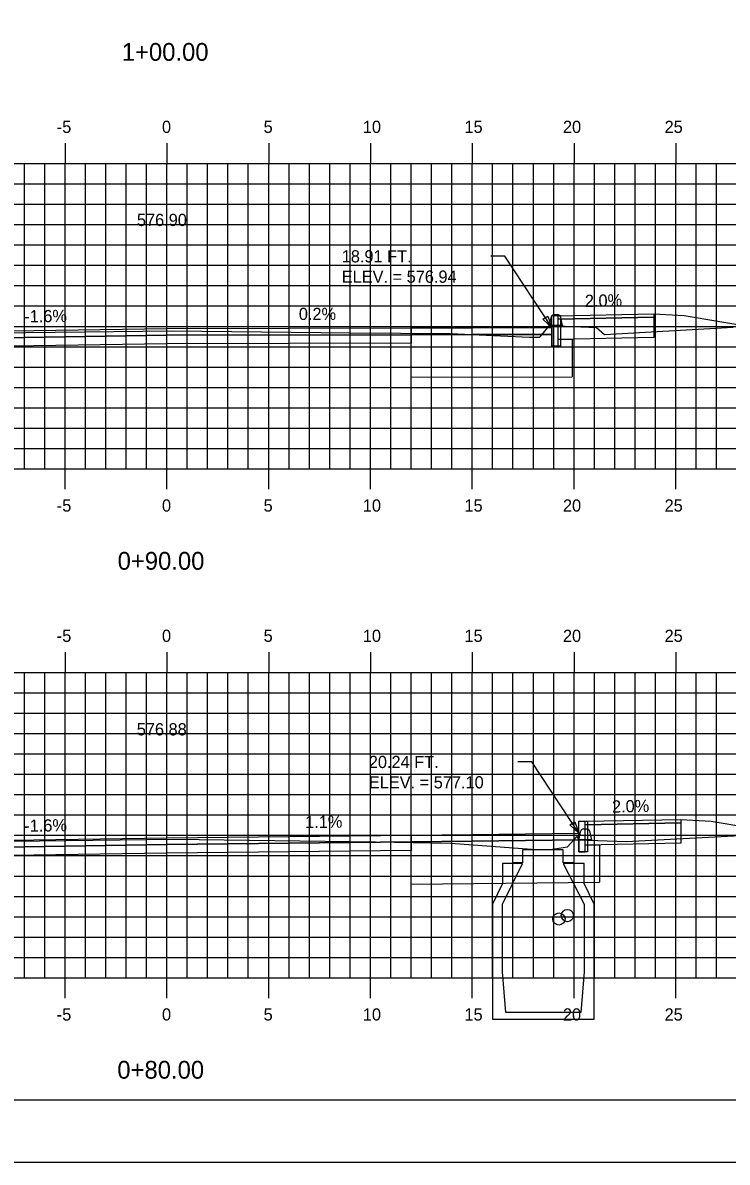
# Model space of a CAD drawing. Extents: x 1048565 to 1048735, y 781387 to 781497.
# Drawn here: x 1048640.8 to 1048675.4, y 781387.3 to 781443.3 of the extents above; entities that cross this region are included whole.
import ezdxf

# ---------------------------------------------------------------- set-up
doc = ezdxf.new("R2010")
doc.units = 0
for name, color, linetype in [('ANNOTATION', 7, 'Continuous'), ('BORDER', 7, 'Continuous'), ('D_Curb_Type1_Lt', 7, 'Continuous'), ('D_Roadway_Berm', 7, 'Continuous'), ('D_Roadway_Centerline', 7, 'Continuous'), ('D_Roadway_Centerline_Text', 7, 'Continuous'), ('D_Roadway_Edge_Shoulder', 7, 'Continuous'), ('D_Roadway_Edge_TW', 7, 'Continuous'), ('D_Roadway_Pavement', 7, 'Continuous'), ('D_Roadway_Sidewalks_Paved', 7, 'Continuous'), ('D_Roadway_SlopeLines', 7, 'Continuous'), ('D_Roadway_SubGrade', 7, 'Continuous'), ('D_Text_Standard', 7, 'Continuous'), ('H_V ANNOTATION', 7, 'Continuous'), ('MAJOR', 7, 'Continuous'), ('MINOR', 7, 'Continuous'), ('PLOT BOUNDARY', 7, 'Continuous'), ('S_Curb_Type_3', 7, 'Continuous'), ('S_Drainage_CB', 7, 'Continuous'), ('S_Drainage_Invert', 7, 'Continuous'), ('S_Roadway_Centerline', 7, 'Continuous')]:
    doc.layers.add(name, color=color, linetype=linetype)

msp = doc.modelspace()

# ---------------------------------------------------------------- linework, layer by layer
at = {"layer": 'BORDER'}
msp.add_lwpolyline([(1048572.876, 781390.375), (1048732.876, 781390.375), (1048732.876, 781495.375), (1048572.876, 781495.375)], close=True, dxfattribs=at)
at = {"layer": 'D_Curb_Type1_Lt'}
for points in [[(1048667.204, 781428.902), (1048667.204, 781427.402), (1048666.787, 781427.402), (1048666.787, 781428.902)], [(1048668.534, 781404.063), (1048668.534, 781402.563), (1048668.117, 781402.563), (1048668.117, 781404.063)]]:
    msp.add_lwpolyline(points, close=True, dxfattribs=at)
at = {"layer": 'D_Roadway_Berm'}
for points in [[(1048671.788, 781428.993), (1048673.288, 781428.903)], [(1048673.118, 781404.155), (1048674.618, 781404.065)]]:
    msp.add_lwpolyline(points, dxfattribs=at)
at = {"layer": 'D_Roadway_Edge_Shoulder'}
for points in [[(1048659.876, 781428.3), (1048662.876, 781428.307), (1048666.787, 781428.316), (1048666.787, 781427.983), (1048662.876, 781427.973), (1048659.876, 781427.966)], [(1048659.876, 781403.385), (1048662.876, 781403.419), (1048668.117, 781403.478), (1048668.117, 781403.144), (1048662.876, 781403.086), (1048659.876, 781403.052)]]:
    msp.add_lwpolyline(points, close=True, dxfattribs=at)
at = {"layer": 'D_Roadway_Edge_TW'}
for points in [[(1048635.876, 781427.752), (1048635.876, 781428.085), (1048647.876, 781428.271), (1048659.876, 781428.3), (1048659.876, 781427.966), (1048647.876, 781427.938)], [(1048635.876, 781402.73), (1048635.876, 781403.063), (1048647.876, 781403.251), (1048659.876, 781403.385), (1048659.876, 781403.052), (1048647.876, 781402.918)]]:
    msp.add_lwpolyline(points, close=True, dxfattribs=at)
at = {"layer": 'D_Roadway_Pavement'}
for points in [[(1048635.876, 781427.335), (1048635.876, 781427.752), (1048647.876, 781427.938), (1048659.876, 781427.966), (1048659.876, 781427.55), (1048647.876, 781427.521)], [(1048635.876, 781402.314), (1048635.876, 781402.73), (1048647.876, 781402.918), (1048659.876, 781403.052), (1048659.876, 781402.636), (1048647.876, 781402.501)]]:
    msp.add_lwpolyline(points, close=True, dxfattribs=at)
at = {"layer": 'D_Roadway_Sidewalks_Paved'}
for points in [[(1048667.088, 781428.899), (1048671.788, 781428.993), (1048671.788, 781428.826), (1048667.088, 781428.732)], [(1048668.418, 781404.061), (1048673.118, 781404.155), (1048673.118, 781403.988), (1048668.418, 781403.894)]]:
    msp.add_lwpolyline(points, close=True, dxfattribs=at)
at = {"layer": 'D_Roadway_SlopeLines'}
for points in [[(1048673.288, 781428.903), (1048676.593, 781428.352)], [(1048674.618, 781404.065), (1048678.119, 781403.481)]]:
    msp.add_lwpolyline(points, dxfattribs=at)
at = {"layer": 'D_Roadway_SubGrade'}
for p, q in [((1048659.876, 781425.883), (1048667.787, 781425.902)), ((1048659.876, 781400.969), (1048669.117, 781401.072))]:
    msp.add_line(p, q, dxfattribs=at)
for points in [[(1048667.088, 781428.732), (1048671.788, 781428.826), (1048671.788, 781427.826), (1048667.088, 781427.732)], [(1048668.418, 781403.894), (1048673.118, 781403.988), (1048673.118, 781402.988), (1048668.418, 781402.894)]]:
    msp.add_lwpolyline(points, close=True, dxfattribs=at)
for points in [[(1048659.876, 781425.883), (1048659.876, 781427.966), (1048659.876, 781427.966), (1048662.876, 781427.973), (1048666.787, 781427.983), (1048666.787, 781427.399), (1048667.097, 781427.399), (1048667.088, 781427.732), (1048667.787, 781427.746), (1048667.787, 781425.902)], [(1048659.876, 781400.969), (1048659.876, 781403.052), (1048659.876, 781403.052), (1048662.876, 781403.086), (1048668.117, 781403.144), (1048668.117, 781402.561), (1048668.427, 781402.561), (1048668.418, 781402.894), (1048669.117, 781402.908), (1048669.117, 781401.072)]]:
    msp.add_lwpolyline(points, dxfattribs=at)
at = {"layer": 'D_Text_Standard'}
for points in [[(1048666.787, 781428.316), (1048664.47, 781431.816), (1048663.79, 781431.816)], [(1048668.117, 781403.478), (1048665.8, 781406.978), (1048665.12, 781406.978)]]:
    msp.add_lwpolyline(points, dxfattribs=at)
for points in [[(1048666.787, 781428.316), (1048666.344, 781428.721), (1048666.587, 781428.882)], [(1048668.117, 781403.478), (1048667.675, 781403.883), (1048667.917, 781404.043)]]:
    msp.add_lwpolyline(points, close=True, dxfattribs=at)
at = {"layer": 'MAJOR'}
for p, q in [((1048642.876, 781437.377), (1048642.876, 781436.375)), ((1048647.876, 781437.377), (1048647.876, 781436.375)), ((1048652.876, 781437.377), (1048652.876, 781436.375)), ((1048657.876, 781437.377), (1048657.876, 781436.375)), ((1048662.876, 781437.377), (1048662.876, 781436.375)), ((1048667.876, 781437.377), (1048667.876, 781436.375)), ((1048672.876, 781437.377), (1048672.876, 781436.375)), ((1048577.876, 781436.375), (1048717.876, 781436.375)), ((1048577.876, 781436.375), (1048717.876, 781436.375)), ((1048642.876, 781421.375), (1048642.876, 781436.375)), ((1048647.876, 781421.375), (1048647.876, 781436.375)), ((1048652.876, 781421.375), (1048652.876, 781436.375)), ((1048657.876, 781421.375), (1048657.876, 781436.375)), ((1048662.876, 781421.375), (1048662.876, 781436.375)), ((1048667.876, 781421.375), (1048667.876, 781436.375)), ((1048672.876, 781421.375), (1048672.876, 781436.375)), ((1048577.876, 781431.375), (1048717.876, 781431.375)), ((1048577.876, 781426.375), (1048717.876, 781426.375)), ((1048577.876, 781421.375), (1048717.876, 781421.375)), ((1048577.876, 781421.375), (1048717.876, 781421.375)), ((1048642.876, 781420.373), (1048642.876, 781421.375)), ((1048647.876, 781420.373), (1048647.876, 781421.375)), ((1048652.876, 781420.373), (1048652.876, 781421.375)), ((1048657.876, 781420.373), (1048657.876, 781421.375)), ((1048662.876, 781420.373), (1048662.876, 781421.375)), ((1048667.876, 781420.373), (1048667.876, 781421.375)), ((1048672.876, 781420.373), (1048672.876, 781421.375)), ((1048642.876, 781412.377), (1048642.876, 781411.375)), ((1048647.876, 781412.377), (1048647.876, 781411.375)), ((1048652.876, 781412.377), (1048652.876, 781411.375)), ((1048657.876, 781412.377), (1048657.876, 781411.375)), ((1048662.876, 781412.377), (1048662.876, 781411.375)), ((1048667.876, 781412.377), (1048667.876, 781411.375)), ((1048672.876, 781412.377), (1048672.876, 781411.375)), ((1048577.876, 781411.375), (1048717.876, 781411.375)), ((1048577.876, 781411.375), (1048717.876, 781411.375)), ((1048642.876, 781396.375), (1048642.876, 781411.375)), ((1048647.876, 781396.375), (1048647.876, 781411.375)), ((1048652.876, 781396.375), (1048652.876, 781411.375)), ((1048657.876, 781396.375), (1048657.876, 781411.375)), ((1048662.876, 781396.375), (1048662.876, 781411.375)), ((1048667.876, 781396.375), (1048667.876, 781411.375)), ((1048672.876, 781396.375), (1048672.876, 781411.375)), ((1048577.876, 781406.375), (1048717.876, 781406.375)), ((1048577.876, 781401.375), (1048717.876, 781401.375)), ((1048577.876, 781396.375), (1048717.876, 781396.375)), ((1048577.876, 781396.375), (1048717.876, 781396.375)), ((1048642.876, 781395.373), (1048642.876, 781396.375)), ((1048647.876, 781395.373), (1048647.876, 781396.375)), ((1048652.876, 781395.373), (1048652.876, 781396.375)), ((1048657.876, 781395.373), (1048657.876, 781396.375)), ((1048662.876, 781395.373), (1048662.876, 781396.375)), ((1048667.876, 781395.373), (1048667.876, 781396.375)), ((1048672.876, 781395.373), (1048672.876, 781396.375))]:
    msp.add_line(p, q, dxfattribs=at)
at = {"layer": 'MINOR'}
for p, q in [((1048640.876, 781421.375), (1048640.876, 781436.375)), ((1048641.876, 781421.375), (1048641.876, 781436.375)), ((1048643.876, 781421.375), (1048643.876, 781436.375)), ((1048644.876, 781421.375), (1048644.876, 781436.375)), ((1048645.876, 781421.375), (1048645.876, 781436.375)), ((1048646.876, 781421.375), (1048646.876, 781436.375)), ((1048648.876, 781421.375), (1048648.876, 781436.375)), ((1048649.876, 781421.375), (1048649.876, 781436.375)), ((1048650.876, 781421.375), (1048650.876, 781436.375)), ((1048651.876, 781421.375), (1048651.876, 781436.375)), ((1048653.876, 781421.375), (1048653.876, 781436.375)), ((1048654.876, 781421.375), (1048654.876, 781436.375)), ((1048655.876, 781421.375), (1048655.876, 781436.375)), ((1048656.876, 781421.375), (1048656.876, 781436.375)), ((1048658.876, 781421.375), (1048658.876, 781436.375)), ((1048659.876, 781421.375), (1048659.876, 781436.375)), ((1048660.876, 781421.375), (1048660.876, 781436.375)), ((1048661.876, 781421.375), (1048661.876, 781436.375)), ((1048663.876, 781421.375), (1048663.876, 781436.375)), ((1048664.876, 781421.375), (1048664.876, 781436.375)), ((1048665.876, 781421.375), (1048665.876, 781436.375)), ((1048666.876, 781421.375), (1048666.876, 781436.375)), ((1048668.876, 781421.375), (1048668.876, 781436.375)), ((1048669.876, 781421.375), (1048669.876, 781436.375)), ((1048670.876, 781421.375), (1048670.876, 781436.375)), ((1048671.876, 781421.375), (1048671.876, 781436.375)), ((1048673.876, 781421.375), (1048673.876, 781436.375)), ((1048674.876, 781421.375), (1048674.876, 781436.375)), ((1048577.876, 781435.375), (1048717.876, 781435.375)), ((1048577.876, 781434.375), (1048717.876, 781434.375)), ((1048577.876, 781433.375), (1048717.876, 781433.375)), ((1048577.876, 781432.375), (1048717.876, 781432.375)), ((1048577.876, 781430.375), (1048717.876, 781430.375)), ((1048577.876, 781429.375), (1048717.876, 781429.375)), ((1048577.876, 781428.375), (1048717.876, 781428.375)), ((1048577.876, 781427.375), (1048717.876, 781427.375)), ((1048577.876, 781425.375), (1048717.876, 781425.375)), ((1048577.876, 781424.375), (1048717.876, 781424.375)), ((1048577.876, 781423.375), (1048717.876, 781423.375)), ((1048577.876, 781422.375), (1048717.876, 781422.375)), ((1048640.876, 781396.375), (1048640.876, 781411.375)), ((1048641.876, 781396.375), (1048641.876, 781411.375)), ((1048643.876, 781396.375), (1048643.876, 781411.375)), ((1048644.876, 781396.375), (1048644.876, 781411.375)), ((1048645.876, 781396.375), (1048645.876, 781411.375)), ((1048646.876, 781396.375), (1048646.876, 781411.375)), ((1048648.876, 781396.375), (1048648.876, 781411.375)), ((1048649.876, 781396.375), (1048649.876, 781411.375)), ((1048650.876, 781396.375), (1048650.876, 781411.375)), ((1048651.876, 781396.375), (1048651.876, 781411.375)), ((1048653.876, 781396.375), (1048653.876, 781411.375)), ((1048654.876, 781396.375), (1048654.876, 781411.375)), ((1048655.876, 781396.375), (1048655.876, 781411.375)), ((1048656.876, 781396.375), (1048656.876, 781411.375)), ((1048658.876, 781396.375), (1048658.876, 781411.375)), ((1048659.876, 781396.375), (1048659.876, 781411.375)), ((1048660.876, 781396.375), (1048660.876, 781411.375)), ((1048661.876, 781396.375), (1048661.876, 781411.375)), ((1048663.876, 781396.375), (1048663.876, 781411.375)), ((1048664.876, 781396.375), (1048664.876, 781411.375)), ((1048665.876, 781396.375), (1048665.876, 781411.375)), ((1048666.876, 781396.375), (1048666.876, 781411.375)), ((1048668.876, 781396.375), (1048668.876, 781411.375)), ((1048669.876, 781396.375), (1048669.876, 781411.375)), ((1048670.876, 781396.375), (1048670.876, 781411.375)), ((1048671.876, 781396.375), (1048671.876, 781411.375)), ((1048673.876, 781396.375), (1048673.876, 781411.375)), ((1048674.876, 781396.375), (1048674.876, 781411.375)), ((1048577.876, 781410.375), (1048717.876, 781410.375)), ((1048577.876, 781409.375), (1048717.876, 781409.375)), ((1048577.876, 781408.375), (1048717.876, 781408.375)), ((1048577.876, 781407.375), (1048717.876, 781407.375)), ((1048577.876, 781405.375), (1048717.876, 781405.375)), ((1048577.876, 781404.375), (1048717.876, 781404.375)), ((1048577.876, 781403.375), (1048717.876, 781403.375)), ((1048577.876, 781402.375), (1048717.876, 781402.375)), ((1048577.876, 781400.375), (1048717.876, 781400.375)), ((1048577.876, 781399.375), (1048717.876, 781399.375)), ((1048577.876, 781398.375), (1048717.876, 781398.375)), ((1048577.876, 781397.375), (1048717.876, 781397.375))]:
    msp.add_line(p, q, dxfattribs=at)
at = {"layer": 'PLOT BOUNDARY'}
msp.add_lwpolyline([(1048564.783, 781387.316), (1048734.783, 781387.316), (1048734.783, 781497.316), (1048564.783, 781497.316)], close=True, dxfattribs=at)
at = {"layer": 'S_Curb_Type_3'}
for points in [[(1048667.188, 781428.854), (1048667.29, 781428.409), (1048666.665, 781428.409), (1048666.768, 781428.854)], [(1048666.89, 781428.951), (1048667.066, 781428.951)], [(1048668.635, 781403.595), (1048668.738, 781403.15), (1048668.113, 781403.15), (1048668.216, 781403.595)], [(1048668.337, 781403.691), (1048668.514, 781403.691)]]:
    msp.add_lwpolyline(points, dxfattribs=at)
for centre, start, end in [((1048666.89, 781428.826), 90, 167.0054), ((1048667.066, 781428.826), 12.9946, 90), ((1048668.337, 781403.566), 90, 167.0054), ((1048668.514, 781403.566), 12.9946, 90)]:
    msp.add_arc(centre, 0.125, start, end, dxfattribs=at)
at = {"layer": 'S_Drainage_CB'}
for p, q in [((1048665.347, 781401.988), (1048664.362, 781401.988)), ((1048664.362, 781401.988), (1048664.362, 781401.004)), ((1048664.362, 781399.987), (1048665.347, 781401.988)), ((1048668.365, 781401.988), (1048667.348, 781401.988)), ((1048667.348, 781401.988), (1048668.365, 781399.987)), ((1048668.365, 781401.004), (1048668.365, 781401.988)), ((1048664.362, 781401.004), (1048663.87, 781399.987)), ((1048668.857, 781399.987), (1048668.365, 781401.004)), ((1048663.87, 781399.987), (1048663.87, 781394.344)), ((1048664.362, 781396.674), (1048664.362, 781399.987)), ((1048668.365, 781399.987), (1048668.365, 781396.674)), ((1048668.857, 781394.344), (1048668.857, 781399.987)), ((1048664.526, 781394.672), (1048664.362, 781396.674)), ((1048668.365, 781396.674), (1048668.201, 781394.672)), ((1048668.201, 781394.672), (1048664.526, 781394.672)), ((1048663.87, 781394.344), (1048668.857, 781394.344))]:
    msp.add_line(p, q, dxfattribs=at)
msp.add_lwpolyline([(1048667.84, 781402.03), (1048667.348, 781402.03), (1048667.348, 781402.653), (1048665.347, 781402.653), (1048665.347, 781402.03), (1048664.854, 781402.03)], dxfattribs=at)
at = {"layer": 'S_Drainage_Invert'}
for centre in [(1048667.131, 781399.264), (1048667.546, 781399.432)]:
    msp.add_circle(centre, 0.3, dxfattribs=at)
at = {"layer": 'S_Roadway_Centerline'}
for points in [[(1048603.553, 781427.592), (1048609.595, 781427.511), (1048612.565, 781427.554), (1048618.245, 781427.637), (1048621.117, 781427.687), (1048622.407, 781427.72), (1048625.009, 781427.781), (1048626.379, 781427.798), (1048629.011, 781427.846), (1048634.632, 781427.977), (1048635.74, 781428.013), (1048636.618, 781428.019), (1048648.138, 781428.155), (1048656.906, 781428.049), (1048661.788, 781428.023), (1048665.69, 781427.845), (1048666.193, 781427.839), (1048666.299, 781427.959), (1048666.665, 781428.409), (1048668.971, 781428.316), (1048669.378, 781427.97), (1048675.683, 781428.333)], [(1048599.349, 781402.799), (1048610.135, 781402.743), (1048610.142, 781402.743), (1048612.266, 781402.671), (1048617.687, 781402.752), (1048625.292, 781402.828), (1048627.022, 781402.905), (1048630.608, 781402.949), (1048635.094, 781402.972), (1048640.296, 781403.09), (1048648.215, 781403.183), (1048658.124, 781403.062), (1048661.819, 781402.987), (1048665.783, 781402.694), (1048666.704, 781402.682), (1048667.556, 781402.811), (1048668.005, 781403.321), (1048668.113, 781403.15), (1048670.427, 781403.069), (1048678.84, 781403.52)]]:
    msp.add_lwpolyline(points, dxfattribs=at)

# ---------------------------------------------------------------- texts
at = {"layer": 'ANNOTATION'}
for s, rotation, p in [('2.0%', 1.1458, (1048668.413, 781429.326)), ('-1.6%', 0.8898, (1048640.875, 781428.563)), ('0.2%', 0.1348, (1048654.357, 781428.687)), ('2.0%', 1.1458, (1048669.744, 781404.488)), ('-1.6%', 0.897, (1048640.875, 781403.542)), ('1.1%', 0.6403, (1048654.669, 781403.727))]:
    msp.add_text(s, height=0.6, rotation=rotation, dxfattribs=at).set_placement(p)
at = {"layer": 'D_Roadway_Centerline'}
for s, p in [('C', (1048647.871, 781428.271)), ('L', (1048647.876, 781428.264)), ('C', (1048647.871, 781403.251)), ('L', (1048647.876, 781403.244))]:
    msp.add_text(s, height=0.0146, dxfattribs=at).set_placement(p)
at = {"layer": 'D_Roadway_Centerline_Text'}
for s, p in [('576.90', (1048646.404, 781433.303)), ('576.88', (1048646.396, 781408.283))]:
    msp.add_text(s, height=0.6, dxfattribs=at).set_placement(p)
at = {"layer": 'D_Text_Standard'}
for s, p in [('18.91 FT.', (1048656.464, 781431.516)), ('ELEV. = 576.94', (1048656.464, 781430.516)), ('20.24 FT.', (1048657.794, 781406.678)), ('ELEV. = 577.10', (1048657.794, 781405.678))]:
    msp.add_text(s, height=0.6, dxfattribs=at).set_placement(p)
at = {"layer": 'H_V ANNOTATION'}
for s, height, p in [('1+00.00', 0.875, (1048645.66, 781441.419)), ('-5', 0.6, (1048642.467, 781437.875)), ('0', 0.6, (1048647.635, 781437.875)), ('5', 0.6, (1048652.627, 781437.875)), ('10', 0.6, (1048657.501, 781437.875)), ('15', 0.6, (1048662.493, 781437.875)), ('20', 0.6, (1048667.33, 781437.875)), ('25', 0.6, (1048672.322, 781437.875)), ('-5', 0.6, (1048642.467, 781419.275)), ('0', 0.6, (1048647.635, 781419.275)), ('5', 0.6, (1048652.627, 781419.275)), ('10', 0.6, (1048657.501, 781419.275)), ('15', 0.6, (1048662.493, 781419.275)), ('20', 0.6, (1048667.33, 781419.275)), ('25', 0.6, (1048672.322, 781419.275)), ('0+90.00', 0.875, (1048645.457, 781416.419)), ('-5', 0.6, (1048642.467, 781412.875)), ('0', 0.6, (1048647.635, 781412.875)), ('5', 0.6, (1048652.627, 781412.875)), ('10', 0.6, (1048657.501, 781412.875)), ('15', 0.6, (1048662.493, 781412.875)), ('20', 0.6, (1048667.33, 781412.875)), ('25', 0.6, (1048672.322, 781412.875)), ('-5', 0.6, (1048642.467, 781394.275)), ('0', 0.6, (1048647.635, 781394.275)), ('5', 0.6, (1048652.627, 781394.275)), ('10', 0.6, (1048657.501, 781394.275)), ('15', 0.6, (1048662.493, 781394.275)), ('20', 0.6, (1048667.33, 781394.275)), ('25', 0.6, (1048672.322, 781394.275)), ('0+80.00', 0.875, (1048645.441, 781391.419))]:
    msp.add_text(s, height=height, dxfattribs=at).set_placement(p)
at = {"layer": 'S_Roadway_Centerline'}
for s, p in [('C', (1048648.132, 781428.155)), ('L', (1048648.138, 781428.148)), ('C', (1048648.21, 781403.183)), ('L', (1048648.215, 781403.176))]:
    msp.add_text(s, height=0.0146, dxfattribs=at).set_placement(p)

doc.saveas('drawing.dxf')
